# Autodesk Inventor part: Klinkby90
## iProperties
Created: 2010-01
Part Number: Klinkby90
Document SubType Name: Modeling
Designer: TB
Mass: 1733 g
Surface Area: 1471.24 cm^2
Volume: 1733 cm^3
Density: 1 g/cm^3
Author: TB
